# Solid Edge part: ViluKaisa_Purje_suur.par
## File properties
Author: kaisa
Template: Iso Metric Part.par
Last saved by: kaisa
Revision: 3
Application: Solid Edge
Accuracy: 0.990
Username: kaisa
Face Style: Model Default
Fill Style: Normal
Coef. of Thermal Exp: 0.0
Thermal Conductivity: 0.0
Specific Heat: 0.0
Modulus of Elasticity: 0.0
Poisson's Ratio: 0.0
Yield Stress: 0.0
Ultimate Stress: 0.0
Elongation: 0.0
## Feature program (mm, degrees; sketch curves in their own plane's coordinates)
thicken "Thicken_1"  Distance1 = 0.5 mm
multibody boolean "unnamed MultibodyBoolean 1"
Other named dimensions: "BlueSurf_2": StartTangentMagnitude1 = 1; StartTangentMagnitude2 = 1; StartTangentMagnitude3 = 1; EndTangentMagnitude1 = 1.4864; EndTangentMagnitude2 = 1.4864; EndTangentMagnitude3 = 1.4864
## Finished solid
Body 1: solid body, 6 faces, 4 edges, 0 vertices, 2 separate solids.
  Faces by surface: plane 4, cylinder 2
  Edges by curve: circle 4
Body 2: solid body, 6 faces, 4 edges, 0 vertices, 2 separate solids.
  Faces by surface: plane 4, cylinder 2
  Edges by curve: circle 4
Body 3: solid body, 11 faces, 26 edges, 16 vertices.
  Faces by surface: spline 6, cylinder 4, offset 1
  Edges by curve: intersection 14, curve on surface 7, spline 3, line 2
Body 4: sheet body, 1 face, 4 edges, 4 vertices.
  Faces by surface: spline 1
  Edges by curve: line 2, spline 2
Bounding box of the edges (mm; curved faces can reach further): 19.410 x 200.907 x 414.160, from (-10.8427, -96.1101, -113.3667) to (8.5674, 104.7971, 300.7931).
Cylindrical faces by radius (mm): R1.6667 x4, R3 x4
Planar faces by outward normal: +y 2, +z 2, -y 2, -z 2
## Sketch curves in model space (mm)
line (0, 103.7576, 51.3196) -> (0, 80.3624, -55.3013)
line (0, -96.1101, 51.1979) -> (0, -78.0348, -56.8354)
spline (7.3587, 0, 46.6775) -> (13.5824, 0, -23.2179) -> (-9.3122, 0, -89.311)
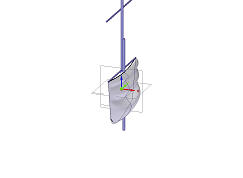
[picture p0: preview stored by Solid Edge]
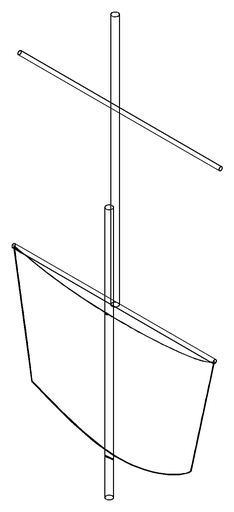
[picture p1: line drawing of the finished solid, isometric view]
